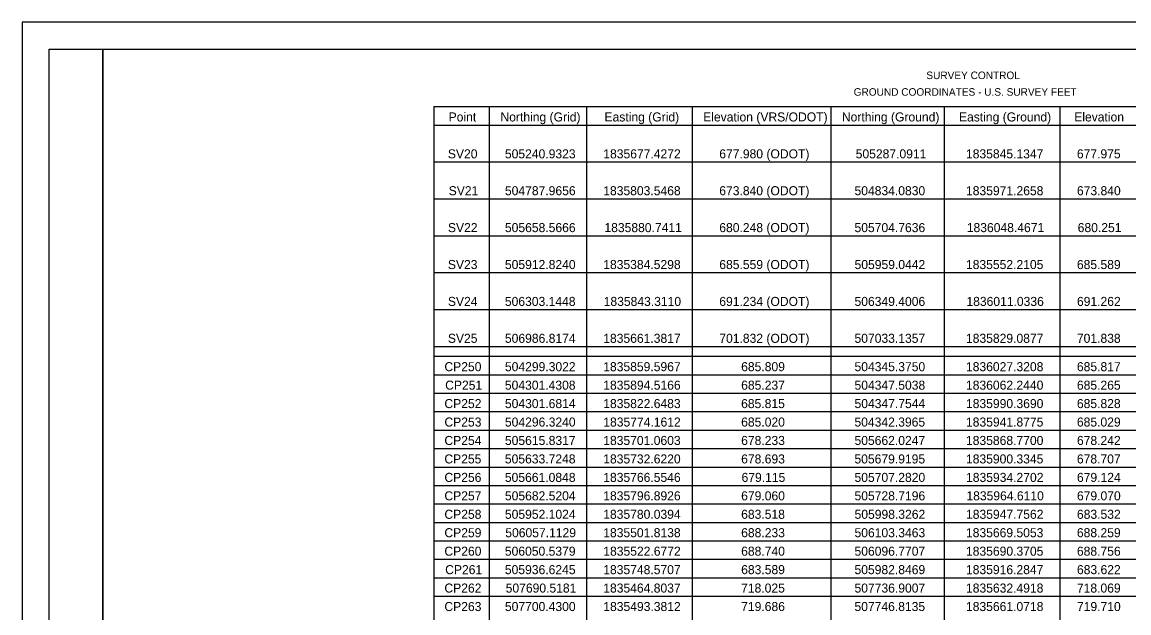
# Model space of a CAD drawing. Extents: x 1835760 to 1838472, y 490734 to 492902.
# Drawn here: x 1838280.77 to 1838301.31, y 491055.33 to 491066.3 of the extents above; entities that cross this region are included whole.
import ezdxf

# ---------------------------------------------------------------- set-up
doc = ezdxf.new("R2010")
doc.units = 0
for name, color, linetype in [('SH_Border', 7, 'Continuous'), ('SH_Cut_Line', 7, 'Continuous'), ('SH_Text', 7, 'Continuous')]:
    doc.layers.add(name, color=color, linetype=linetype)

msp = doc.modelspace()

# ---------------------------------------------------------------- linework, layer by layer
at = {"layer": 'SH_Border'}
for points in [[(1838281.271, 491065.805), (1838282.271, 491065.805), (1838282.271, 491044.805), (1838281.271, 491044.805)], [(1838282.271, 491065.805), (1838314.271, 491065.805), (1838314.271, 491044.805), (1838282.271, 491044.805)]]:
    msp.add_lwpolyline(points, close=True, dxfattribs=at)
at = {"layer": 'SH_Cut_Line'}
msp.add_lwpolyline([(1838280.771, 491044.305), (1838314.771, 491044.305), (1838314.771, 491066.305), (1838280.771, 491066.305)], close=True, dxfattribs=at)
at = {"layer": 'SH_Text'}
for p, q in [((1838288.413, 491064.737), (1838295.779, 491064.737)), ((1838288.413, 491064.737), (1838288.413, 491058.728)), ((1838289.441, 491064.737), (1838289.441, 491058.728)), ((1838291.246, 491064.737), (1838291.246, 491058.728)), ((1838293.209, 491064.737), (1838293.209, 491058.728)), ((1838295.779, 491064.737), (1838300.035, 491064.737)), ((1838295.779, 491064.737), (1838295.779, 491058.728)), ((1838297.887, 491064.737), (1838297.887, 491058.728)), ((1838300.035, 491064.737), (1838305.081, 491064.737)), ((1838300.035, 491064.737), (1838300.035, 491058.728)), ((1838288.413, 491064.394), (1838295.779, 491064.394)), ((1838295.779, 491064.394), (1838300.035, 491064.394)), ((1838300.035, 491064.394), (1838305.081, 491064.394)), ((1838288.413, 491063.709), (1838295.779, 491063.709)), ((1838295.779, 491063.709), (1838300.035, 491063.709)), ((1838300.035, 491063.709), (1838305.081, 491063.709)), ((1838288.413, 491063.024), (1838295.779, 491063.024)), ((1838295.779, 491063.024), (1838300.035, 491063.024)), ((1838300.035, 491063.024), (1838305.081, 491063.024)), ((1838288.413, 491062.339), (1838295.779, 491062.339)), ((1838295.779, 491062.339), (1838300.035, 491062.339)), ((1838300.035, 491062.339), (1838305.081, 491062.339)), ((1838288.413, 491061.653), (1838295.779, 491061.653)), ((1838295.779, 491061.653), (1838300.035, 491061.653)), ((1838300.035, 491061.653), (1838305.081, 491061.653)), ((1838288.413, 491060.968), (1838295.779, 491060.968)), ((1838295.779, 491060.968), (1838300.035, 491060.968)), ((1838300.035, 491060.968), (1838305.081, 491060.968)), ((1838288.413, 491060.283), (1838295.779, 491060.283)), ((1838295.779, 491060.283), (1838300.035, 491060.283)), ((1838300.035, 491060.283), (1838305.081, 491060.283)), ((1838288.413, 491060.099), (1838295.779, 491060.099)), ((1838295.779, 491060.099), (1838300.035, 491060.099)), ((1838300.035, 491060.099), (1838305.081, 491060.099)), ((1838288.413, 491059.756), (1838295.779, 491059.756)), ((1838295.779, 491059.756), (1838300.035, 491059.756)), ((1838300.035, 491059.756), (1838305.081, 491059.756)), ((1838288.413, 491059.413), (1838295.779, 491059.413)), ((1838295.779, 491059.413), (1838300.035, 491059.413)), ((1838300.035, 491059.413), (1838305.081, 491059.413)), ((1838288.413, 491059.071), (1838295.779, 491059.071)), ((1838295.779, 491059.071), (1838300.035, 491059.071)), ((1838300.035, 491059.071), (1838305.081, 491059.071)), ((1838288.413, 491058.728), (1838295.779, 491058.728)), ((1838288.413, 491058.728), (1838288.413, 491058.386)), ((1838289.441, 491058.728), (1838289.441, 491058.386)), ((1838291.246, 491058.728), (1838291.246, 491058.386)), ((1838293.209, 491058.728), (1838293.209, 491058.386)), ((1838295.779, 491058.728), (1838300.035, 491058.728)), ((1838295.779, 491058.728), (1838295.779, 491058.386)), ((1838297.887, 491058.728), (1838297.887, 491058.386)), ((1838300.035, 491058.728), (1838305.081, 491058.728)), ((1838300.035, 491058.728), (1838300.035, 491058.386)), ((1838288.413, 491058.386), (1838295.779, 491058.386)), ((1838288.413, 491058.386), (1838288.413, 491057.701)), ((1838289.441, 491058.386), (1838289.441, 491057.701)), ((1838291.246, 491058.386), (1838291.246, 491057.701)), ((1838293.209, 491058.386), (1838293.209, 491057.701)), ((1838295.779, 491058.386), (1838300.035, 491058.386)), ((1838295.779, 491058.386), (1838295.779, 491057.701)), ((1838297.887, 491058.386), (1838297.887, 491057.701)), ((1838300.035, 491058.386), (1838305.081, 491058.386)), ((1838300.035, 491058.386), (1838300.035, 491057.701)), ((1838288.413, 491058.043), (1838295.779, 491058.043)), ((1838295.779, 491058.043), (1838300.035, 491058.043)), ((1838300.035, 491058.043), (1838305.081, 491058.043)), ((1838288.413, 491057.701), (1838295.779, 491057.701)), ((1838288.413, 491057.701), (1838288.413, 491057.358)), ((1838289.441, 491057.701), (1838289.441, 491057.358)), ((1838291.246, 491057.701), (1838291.246, 491057.358)), ((1838293.209, 491057.701), (1838293.209, 491057.358)), ((1838295.779, 491057.701), (1838300.035, 491057.701)), ((1838295.779, 491057.701), (1838295.779, 491057.358)), ((1838297.887, 491057.701), (1838297.887, 491057.358)), ((1838300.035, 491057.701), (1838305.081, 491057.701)), ((1838300.035, 491057.701), (1838300.035, 491057.358)), ((1838288.413, 491057.358), (1838295.779, 491057.358)), ((1838288.413, 491057.358), (1838288.413, 491053.247)), ((1838289.441, 491057.358), (1838289.441, 491053.247)), ((1838291.246, 491057.358), (1838291.246, 491053.247)), ((1838293.209, 491057.358), (1838293.209, 491053.247)), ((1838295.779, 491057.358), (1838300.035, 491057.358)), ((1838295.779, 491057.358), (1838295.779, 491053.247)), ((1838297.887, 491057.358), (1838297.887, 491053.247)), ((1838300.035, 491057.358), (1838305.081, 491057.358)), ((1838300.035, 491057.358), (1838300.035, 491053.247)), ((1838288.413, 491057.015), (1838295.779, 491057.015)), ((1838295.779, 491057.015), (1838300.035, 491057.015)), ((1838300.035, 491057.015), (1838305.081, 491057.015)), ((1838288.413, 491056.673), (1838295.779, 491056.673)), ((1838295.779, 491056.673), (1838300.035, 491056.673)), ((1838300.035, 491056.673), (1838305.081, 491056.673)), ((1838288.413, 491056.33), (1838295.779, 491056.33)), ((1838295.779, 491056.33), (1838300.035, 491056.33)), ((1838300.035, 491056.33), (1838305.081, 491056.33)), ((1838288.413, 491055.988), (1838295.779, 491055.988)), ((1838295.779, 491055.988), (1838300.035, 491055.988)), ((1838300.035, 491055.988), (1838305.081, 491055.988)), ((1838288.413, 491055.645), (1838295.779, 491055.645)), ((1838295.779, 491055.645), (1838300.035, 491055.645)), ((1838300.035, 491055.645), (1838305.081, 491055.645))]:
    msp.add_line(p, q, dxfattribs=at)

# ---------------------------------------------------------------- texts
for s, height, p in [('SURVEY CONTROL', 0.14, (1838297.554, 491065.247)), ('GROUND COORDINATES - U.S. SURVEY FEET', 0.14, (1838296.205, 491064.938)), ('Point', 0.168, (1838288.687, 491064.46)), ('Northing (Grid)', 0.168, (1838289.649, 491064.46)), ('Easting (Grid)', 0.168, (1838291.58, 491064.46)), ('Elevation (VRS/ODOT)', 0.168, (1838293.412, 491064.46)), ('Northing (Ground)', 0.168, (1838295.986, 491064.46)), ('Easting (Ground)', 0.168, (1838298.16, 491064.46)), ('Elevation', 0.168, (1838300.299, 491064.46)), ('SV20', 0.168, (1838288.673, 491063.775)), ('505240.9323', 0.168, (1838289.732, 491063.775)), ('1835677.4272', 0.168, (1838291.558, 491063.775)), ('677.980 (ODOT)', 0.168, (1838293.711, 491063.775)), ('505287.0911', 0.168, (1838296.243, 491063.775)), ('1835845.1347', 0.168, (1838298.29, 491063.775)), ('677.975', 0.168, (1838300.349, 491063.775)), ('SV21', 0.168, (1838288.688, 491063.09)), ('504787.9656', 0.168, (1838289.732, 491063.09)), ('1835803.5468', 0.168, (1838291.557, 491063.09)), ('673.840 (ODOT)', 0.168, (1838293.711, 491063.09)), ('504834.0830', 0.168, (1838296.221, 491063.09)), ('1835971.2658', 0.168, (1838298.29, 491063.09)), ('673.840', 0.168, (1838300.35, 491063.09)), ('SV22', 0.168, (1838288.674, 491062.405)), ('505658.5666', 0.168, (1838289.732, 491062.405)), ('1835880.7411', 0.168, (1838291.579, 491062.405)), ('680.248 (ODOT)', 0.168, (1838293.711, 491062.405)), ('505704.7636', 0.168, (1838296.221, 491062.405)), ('1836048.4671', 0.168, (1838298.305, 491062.405)), ('680.251', 0.168, (1838300.364, 491062.405)), ('SV23', 0.168, (1838288.673, 491061.719)), ('505912.8240', 0.168, (1838289.732, 491061.719)), ('1835384.5298', 0.168, (1838291.557, 491061.719)), ('685.559 (ODOT)', 0.168, (1838293.711, 491061.719)), ('505959.0442', 0.168, (1838296.222, 491061.719)), ('1835552.2105', 0.168, (1838298.29, 491061.719)), ('685.589', 0.168, (1838300.349, 491061.719)), ('SV24', 0.168, (1838288.673, 491061.034)), ('506303.1448', 0.168, (1838289.731, 491061.034)), ('1835843.3110', 0.168, (1838291.565, 491061.034)), ('691.234 (ODOT)', 0.168, (1838293.711, 491061.034)), ('506349.4006', 0.168, (1838296.221, 491061.034)), ('1836011.0336', 0.168, (1838298.298, 491061.034)), ('691.262', 0.168, (1838300.35, 491061.034)), ('SV25', 0.168, (1838288.673, 491060.349)), ('506986.8174', 0.168, (1838289.732, 491060.349)), ('1835661.3817', 0.168, (1838291.557, 491060.349)), ('701.832 (ODOT)', 0.168, (1838293.711, 491060.349)), ('507033.1357', 0.168, (1838296.221, 491060.349)), ('1835829.0877', 0.168, (1838298.29, 491060.349)), ('701.838', 0.168, (1838300.349, 491060.349)), ('CP250', 0.168, (1838288.609, 491059.822)), ('504299.3022', 0.168, (1838289.732, 491059.822)), ('1835859.5967', 0.168, (1838291.557, 491059.822)), ('685.809', 0.168, (1838294.117, 491059.822)), ('504345.3750', 0.168, (1838296.221, 491059.822)), ('1836027.3208', 0.168, (1838298.29, 491059.822)), ('685.817', 0.168, (1838300.349, 491059.822)), ('CP251', 0.168, (1838288.623, 491059.479)), ('504301.4308', 0.168, (1838289.731, 491059.479)), ('1835894.5166', 0.168, (1838291.557, 491059.479)), ('685.237', 0.168, (1838294.117, 491059.479)), ('504347.5038', 0.168, (1838296.221, 491059.479)), ('1836062.2440', 0.168, (1838298.29, 491059.479)), ('685.265', 0.168, (1838300.349, 491059.479)), ('CP252', 0.168, (1838288.609, 491059.137)), ('504301.6814', 0.168, (1838289.732, 491059.137)), ('1835822.6483', 0.168, (1838291.557, 491059.137)), ('685.815', 0.168, (1838294.116, 491059.137)), ('504347.7544', 0.168, (1838296.221, 491059.137)), ('1835990.3690', 0.168, (1838298.29, 491059.137)), ('685.828', 0.168, (1838300.349, 491059.137)), ('CP253', 0.168, (1838288.609, 491058.794)), ('504296.3240', 0.168, (1838289.732, 491058.794)), ('1835774.1612', 0.168, (1838291.558, 491058.794)), ('685.020', 0.168, (1838294.117, 491058.794)), ('504342.3965', 0.168, (1838296.22, 491058.794)), ('1835941.8775', 0.168, (1838298.29, 491058.794)), ('685.029', 0.168, (1838300.349, 491058.794)), ('CP254', 0.168, (1838288.609, 491058.452)), ('505615.8317', 0.168, (1838289.732, 491058.452)), ('1835701.0603', 0.168, (1838291.557, 491058.452)), ('678.233', 0.168, (1838294.117, 491058.452)), ('505662.0247', 0.168, (1838296.221, 491058.452)), ('1835868.7700', 0.168, (1838298.29, 491058.452)), ('678.242', 0.168, (1838300.35, 491058.452)), ('CP255', 0.168, (1838288.608, 491058.109)), ('505633.7248', 0.168, (1838289.731, 491058.109)), ('1835732.6220', 0.168, (1838291.557, 491058.109)), ('678.693', 0.168, (1838294.117, 491058.109)), ('505679.9195', 0.168, (1838296.22, 491058.109)), ('1835900.3345', 0.168, (1838298.29, 491058.109)), ('678.707', 0.168, (1838300.349, 491058.109)), ('CP256', 0.168, (1838288.609, 491057.766)), ('505661.0848', 0.168, (1838289.731, 491057.766)), ('1835766.5546', 0.168, (1838291.557, 491057.766)), ('679.115', 0.168, (1838294.124, 491057.766)), ('505707.2820', 0.168, (1838296.221, 491057.766)), ('1835934.2702', 0.168, (1838298.291, 491057.766)), ('679.124', 0.168, (1838300.35, 491057.766)), ('CP257', 0.168, (1838288.609, 491057.424)), ('505682.5204', 0.168, (1838289.732, 491057.424)), ('1835796.8926', 0.168, (1838291.557, 491057.424)), ('679.060', 0.168, (1838294.117, 491057.424)), ('505728.7196', 0.168, (1838296.221, 491057.424)), ('1835964.6110', 0.168, (1838298.298, 491057.424)), ('679.070', 0.168, (1838300.35, 491057.424)), ('CP258', 0.168, (1838288.609, 491057.081)), ('505952.1024', 0.168, (1838289.732, 491057.081)), ('1835780.0394', 0.168, (1838291.557, 491057.081)), ('683.518', 0.168, (1838294.117, 491057.081)), ('505998.3262', 0.168, (1838296.222, 491057.081)), ('1835947.7562', 0.168, (1838298.291, 491057.081)), ('683.532', 0.168, (1838300.35, 491057.081)), ('CP259', 0.168, (1838288.609, 491056.739)), ('506057.1129', 0.168, (1838289.739, 491056.739)), ('1835501.8138', 0.168, (1838291.557, 491056.739)), ('688.233', 0.168, (1838294.117, 491056.739)), ('506103.3463', 0.168, (1838296.221, 491056.739)), ('1835669.5053', 0.168, (1838298.29, 491056.739)), ('688.259', 0.168, (1838300.349, 491056.739)), ('CP260', 0.168, (1838288.609, 491056.396)), ('506050.5379', 0.168, (1838289.731, 491056.396)), ('1835522.6772', 0.168, (1838291.558, 491056.396)), ('688.740', 0.168, (1838294.117, 491056.396)), ('506096.7707', 0.168, (1838296.221, 491056.396)), ('1835690.3705', 0.168, (1838298.29, 491056.396)), ('688.756', 0.168, (1838300.349, 491056.396)), ('CP261', 0.168, (1838288.623, 491056.053)), ('505936.6245', 0.168, (1838289.731, 491056.053)), ('1835748.5707', 0.168, (1838291.557, 491056.053)), ('683.589', 0.168, (1838294.117, 491056.053)), ('505982.8469', 0.168, (1838296.221, 491056.053)), ('1835916.2847', 0.168, (1838298.29, 491056.053)), ('683.622', 0.168, (1838300.35, 491056.053)), ('CP262', 0.168, (1838288.609, 491055.711)), ('507690.5181', 0.168, (1838289.746, 491055.711)), ('1835464.8037', 0.168, (1838291.557, 491055.711)), ('718.025', 0.168, (1838294.116, 491055.711)), ('507736.9007', 0.168, (1838296.221, 491055.711)), ('1835632.4918', 0.168, (1838298.29, 491055.711)), ('718.069', 0.168, (1838300.349, 491055.711)), ('CP263', 0.168, (1838288.609, 491055.368)), ('507700.4300', 0.168, (1838289.732, 491055.368)), ('1835493.3812', 0.168, (1838291.558, 491055.368)), ('719.686', 0.168, (1838294.117, 491055.368)), ('507746.8135', 0.168, (1838296.22, 491055.368)), ('1835661.0718', 0.168, (1838298.29, 491055.368)), ('719.710', 0.168, (1838300.35, 491055.368))]:
    msp.add_text(s, height=height, dxfattribs=at).set_placement(p)

doc.saveas('drawing.dxf')
